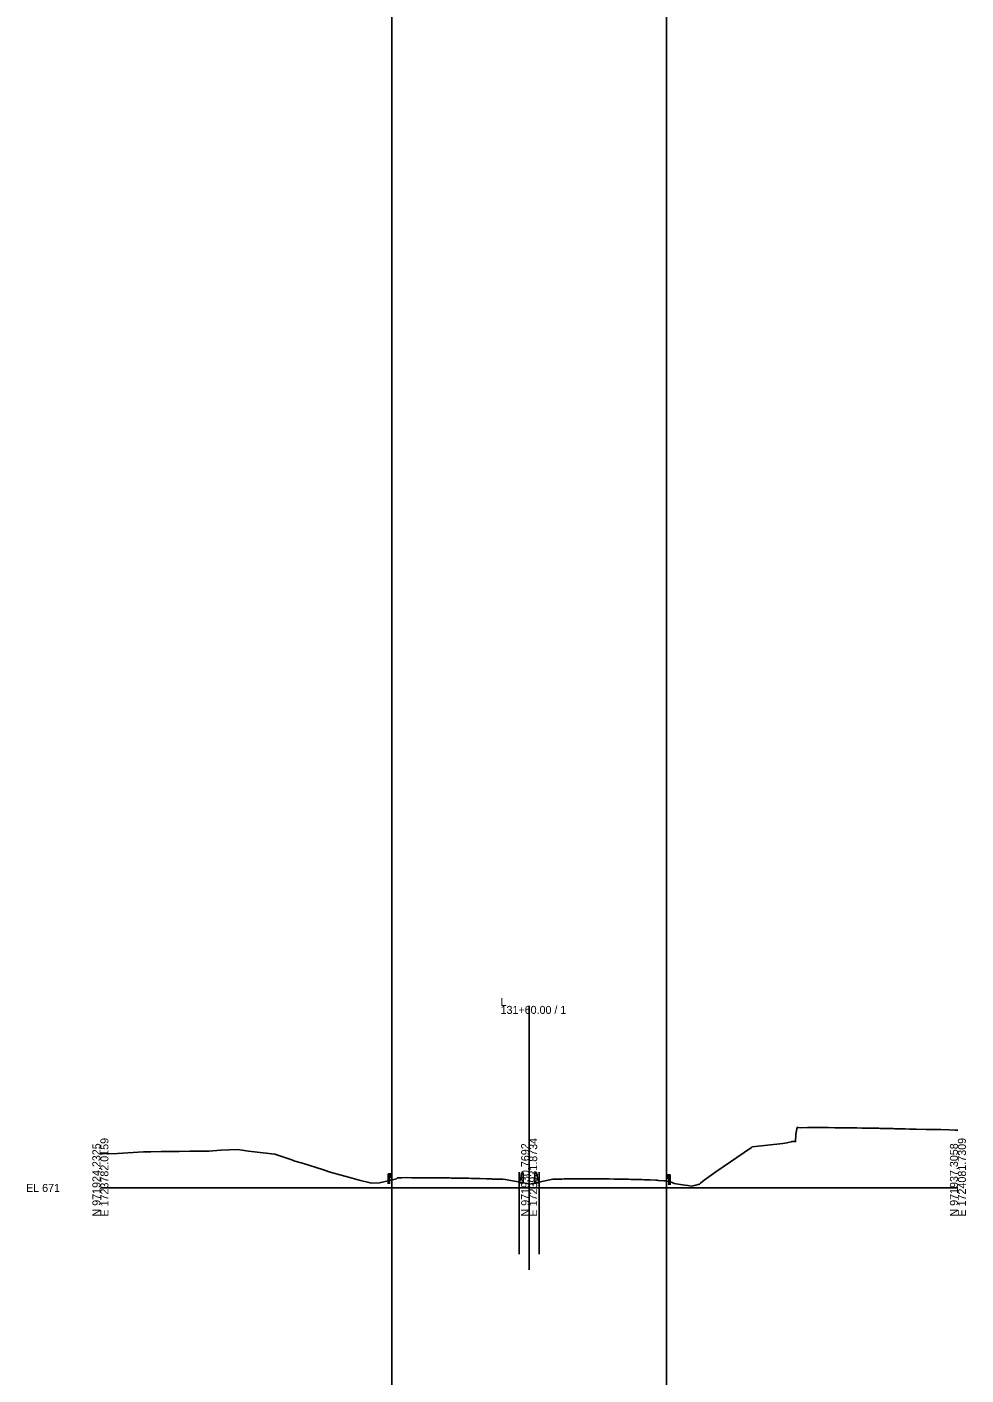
# Model space of a CAD drawing. Extents: x -26 to 303, y -29 to 15026.
# Drawn here: x -25.7 to 302.8, y 5434.6 to 5906.1 of the extents above; entities that cross this region are included whole.
import ezdxf

# ---------------------------------------------------------------- set-up
doc = ezdxf.new("R2010")
doc.units = 0
for name, color, linetype in [('Exist Cross Section Cell', 7, 'Continuous'), ('Exist XS Center Line Elevation Label', 7, 'Continuous'), ('Exist XS Ground Line', 7, 'Continuous'), ('Scratch_Level_0', 7, 'Continuous'), ('Typical Guardrail CELL', 7, 'Continuous'), ('Typical Median Barrier CELL', 7, 'Continuous')]:
    doc.layers.add(name, color=color, linetype=linetype)

msp = doc.modelspace()

# ---------------------------------------------------------------- linework, layer by layer
at = {"layer": 'Exist Cross Section Cell'}
for p, q in [((150, 5500), (150, 5563.68)), ((0, 5500), (150, 5500)), ((150, 5500), (300, 5500))]:
    msp.add_line(p, q, dxfattribs=at)
at = {"layer": 'Exist XS Ground Line'}
msp.add_lwpolyline([(0, 5511.9), (0.55, 5511.92), (5.95, 5512.02), (15.09, 5512.58), (17.59, 5512.59), (21.26, 5512.79), (27.52, 5512.78), (31.25, 5512.88), (38.03, 5512.89), (41.97, 5513.16), (48.04, 5513.41), (51.8, 5512.86), (61, 5511.81), (66.93, 5509.86), (68.06, 5509.41), (70.74, 5508.64), (78.07, 5506.28), (80.34, 5505.52), (88.08, 5503.38), (90.52, 5502.7), (94.34, 5501.76), (95.34, 5501.7), (97.64, 5501.77), (102.67, 5502.97), (103.55, 5503.21), (103.95, 5503.48), (104.75, 5503.52), (105.4, 5503.53), (107.17, 5503.6), (108.86, 5503.59), (109.7, 5503.58), (110.63, 5503.58), (111.26, 5503.59), (111.59, 5503.58), (112.2, 5503.58), (113.23, 5503.57), (114.71, 5503.55), (116.06, 5503.55), (117.21, 5503.54), (118.46, 5503.52), (119.69, 5503.51), (121.04, 5503.49), (122.18, 5503.48), (122.7, 5503.47), (123.05, 5503.47), (123.82, 5503.46), (124.68, 5503.46), (126.28, 5503.42), (127.19, 5503.4), (128.89, 5503.36), (129.68, 5503.34), (131.53, 5503.29), (132.2, 5503.27), (132.81, 5503.25), (135.02, 5503.19), (135.74, 5503.16), (136.86, 5503.13), (137.19, 5503.12), (137.63, 5503.11), (140, 5503.05), (140.77, 5503.02), (141.63, 5502.99), (148.11, 5501.73), (150.15, 5501.35), (151.75, 5501.66), (158.32, 5503.02), (159.25, 5503.05), (159.71, 5503.05), (161.57, 5503.11), (162.24, 5503.13), (162.99, 5503.15), (164.47, 5503.2), (165.52, 5503.19), (167.25, 5503.19), (168.81, 5503.2), (169.76, 5503.21), (171.21, 5503.2), (172.27, 5503.2), (173.41, 5503.2), (174.76, 5503.2), (176.45, 5503.18), (177.27, 5503.17), (177.95, 5503.16), (179.74, 5503.12), (180.77, 5503.1), (182.24, 5503.07), (183.84, 5503.03), (184.73, 5503.01), (185.54, 5502.99), (187.25, 5502.95), (189.46, 5502.9), (190.35, 5502.86), (192.25, 5502.78), (194.33, 5502.68), (194.75, 5502.66), (195.14, 5502.64), (197.13, 5502.52), (197.64, 5502.47), (198.33, 5502.33), (198.9, 5502.24), (200.06, 5501.93), (200.71, 5501.57), (203.64, 5501.1), (204.42, 5501.01), (205.57, 5500.81), (206.72, 5500.63), (207.82, 5500.82), (209.61, 5501.35), (209.97, 5501.68), (211.23, 5502.74), (215.3, 5505.68), (227.74, 5514.11), (228.04, 5514.32), (238.78, 5515.58), (240.16, 5515.72), (241.71, 5516.08), (241.81, 5516.26), (242.23, 5516.25), (243.21, 5516.24), (243.27, 5518.86), (243.76, 5521.23), (244.05, 5521.1), (244.86, 5521.07), (247.34, 5521.1), (249.52, 5521.13), (250.23, 5521.12), (251.39, 5521.11), (251.73, 5521.11), (252.21, 5521.11), (252.56, 5521.1), (254.76, 5521.09), (256.92, 5521.07), (257.22, 5521.07), (259.58, 5521.05), (261.63, 5521.02), (262.08, 5521.02), (264.04, 5520.99), (264.58, 5520.98), (266.44, 5520.96), (267.08, 5520.95), (268.86, 5520.92), (269.59, 5520.91), (270.29, 5520.89), (271.63, 5520.86), (272.34, 5520.85), (272.78, 5520.84), (274.84, 5520.79), (275.42, 5520.78), (277.35, 5520.74), (277.95, 5520.72), (278.81, 5520.7), (280.33, 5520.67), (281.51, 5520.65), (283.08, 5520.61), (285.02, 5520.58), (285.36, 5520.57), (288.86, 5520.48), (289.83, 5520.46), (292.8, 5520.39), (294, 5520.39), (296.78, 5520.3), (299, 5520.24), (300, 5520.23)], dxfattribs=at)
at = {"layer": 'Scratch_Level_0'}
for p, q in [((102, 15009.56), (102, -28.7)), ((198, 15009.56), (198, -28.7)), ((146.46, 5505.5), (146.46, 5476.8)), ((153.54, 5505.5), (153.54, 5476.8)), ((150, 5500), (150, 5471.3)), ((150, 5500), (150, 5471.3))]:
    msp.add_line(p, q, dxfattribs=at)
at = {"layer": 'Typical Guardrail CELL'}
for p, q in [((101.18, 5504.98), (100.68, 5504.98)), ((100.68, 5504.98), (100.68, 5502.5)), ((101.18, 5504.98), (101.18, 5502.5)), ((101.18, 5504.98), (101.68, 5504.98)), ((101.18, 5503.82), (101.68, 5503.82)), ((101.68, 5504.98), (101.68, 5503.82)), ((101.68, 5504.98), (101.97, 5504.78)), ((101.68, 5504.45), (101.97, 5504.65)), ((101.68, 5504.4), (101.68, 5504.45)), ((101.68, 5504.4), (101.68, 5504.36)), ((101.68, 5504.36), (101.97, 5504.15)), ((101.68, 5503.82), (101.97, 5504.03)), ((198.32, 5504.62), (198.03, 5504.41)), ((198.32, 5504.08), (198.03, 5504.29)), ((198.32, 5503.99), (198.03, 5503.79)), ((198.32, 5503.46), (198.03, 5503.66)), ((198.82, 5504.62), (198.32, 5504.62)), ((198.32, 5504.62), (198.32, 5503.46)), ((198.32, 5504.04), (198.32, 5504.08)), ((198.32, 5504.04), (198.32, 5503.99)), ((198.82, 5503.46), (198.32, 5503.46)), ((198.82, 5504.62), (198.82, 5502.13)), ((198.82, 5504.62), (199.32, 5504.62)), ((199.32, 5504.62), (199.32, 5502.13)), ((101.18, 5502.5), (100.68, 5502.5)), ((100.68, 5502.5), (100.68, 5501.49)), ((101.18, 5502.5), (101.18, 5501.49)), ((198.82, 5502.13), (199.32, 5502.13)), ((198.82, 5502.13), (198.82, 5501.12)), ((199.32, 5502.13), (199.32, 5501.12))]:
    msp.add_line(p, q, dxfattribs=at)
for centre, start, end in [((101.92, 5504.72), 304.9888, 54.997), ((101.92, 5504.09), 304.9634, 54.9941), ((198.08, 5504.35), 125.003, 235.0112), ((198.08, 5503.72), 125.0059, 235.0366)]:
    msp.add_arc(centre, 0.0776, start, end, dxfattribs=at)
at = {"layer": 'Typical Median Barrier CELL'}
for p, q in [((147.07, 5503.31), (147.29, 5505.26)), ((147.29, 5505.26), (147.96, 5505.26)), ((147.96, 5505.26), (147.96, 5501.84)), ((152.71, 5505.26), (152.04, 5505.26)), ((152.04, 5505.26), (152.04, 5501.84)), ((152.93, 5503.31), (152.71, 5505.26)), ((146.46, 5502.26), (146.92, 5502.92)), ((146.46, 5501.84), (146.46, 5502.26)), ((147.96, 5501.84), (146.46, 5501.84)), ((152.04, 5501.84), (153.54, 5501.84)), ((153.54, 5502.26), (153.08, 5502.92)), ((153.54, 5501.84), (153.54, 5502.26))]:
    msp.add_line(p, q, dxfattribs=at)
for centre, start, end in [((146.24, 5503.4), 325.0039, 353.9447), ((153.76, 5503.4), 186.0553, 214.9961)]:
    msp.add_arc(centre, 0.833, start, end, dxfattribs=at)

# ---------------------------------------------------------------- texts
at = {"layer": 'Exist Cross Section Cell'}
for s, p in [('L', (140, 5563.68)), ('131+60.00 / 1', (140, 5560.88)), ('EL 671', (-26, 5498.6))]:
    msp.add_text(s, height=2.8, dxfattribs=at).set_placement(p)
for s, p in [('E 1723782.0159', (2.8, 5490)), ('E 1723931.8734', (152.8, 5490)), ('E 1724081.7309', (302.8, 5490)), ('N 971924.2325', (0, 5490)), ('N 971930.7692', (150, 5490)), ('N 971937.3058', (300, 5490))]:
    msp.add_text(s, height=2.8, rotation=90, dxfattribs=at).set_placement(p)
at = {"layer": 'Exist XS Center Line Elevation Label'}
msp.add_text('672.35', height=0.18, dxfattribs=at).set_placement((149.62, 5500.86))

doc.saveas('drawing.dxf')
